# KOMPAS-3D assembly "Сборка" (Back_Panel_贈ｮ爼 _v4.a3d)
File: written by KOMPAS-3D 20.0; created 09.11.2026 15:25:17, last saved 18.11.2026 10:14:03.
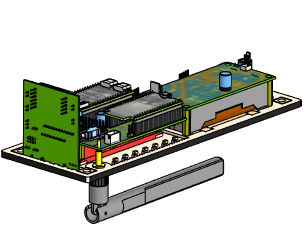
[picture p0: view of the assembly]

Document properties: Полное имя файла: D:\RicWork\Project-EPS32\box_compas\сборки компонентов\Back_Panel_Сборка_v4.a3d

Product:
- Part/product: Сборка
    Масса: 1.56344
  - Component [assembly]: Сборка  | pos. 18  | Масса: 0.0580575; Раздел спецификации: Сборочные единицы; source file: кондуктор под 3 кнопки asm.a3d
  - Component [detail]: Деталь  | pos. 15  | Масса: 0.000148431; Раздел спецификации: Детали; source file: ..\прочее\Латунные рифленые гайки HUI JI.m3d
  - Component [detail]: Деталь  | pos. 16  | Масса: 0.000148431; Раздел спецификации: Детали; source file: ..\прочее\Латунные рифленые гайки HUI JI.m3d
  - Component [detail]: Деталь  | pos. 14  | Масса: 0.000148431; Раздел спецификации: Детали; source file: ..\прочее\Латунные рифленые гайки HUI JI.m3d
  - Component [detail]: Деталь  | pos. 13  | Масса: 0.000148431; Раздел спецификации: Детали; source file: ..\прочее\Латунные рифленые гайки HUI JI.m3d
  - Component [detail]: Деталь  | pos. 10  | Материал: Фанера, береза,ФСФ ВВ/С ГОСТ 3916.1-2018 (density 760 kg/m3); Масса: 0.0215078; Раздел спецификации: Детали; source file: ..\корпус\back_panel_v4.m3d
  - Component [detail]: Деталь  | pos. 1  | Масса: 0.0866709; Раздел спецификации: Детали; source file: ..\корпус\крышка на батарейный отсек v4.m3d
  - Component [detail]: Деталь  | pos. 3  | Масса: 0.0290543; Раздел спецификации: Детали; source file: ..\корпус\крышка на монитор v4.m3d
  - Component [assembly]: Сборка  | pos. 6  | Масса: 0.0719376; Раздел спецификации: Сборочные единицы; source file: панель под энкодеры v4 asm.a3d
  - Component [assembly]: Сборка  | pos. 11  | Масса: 0.120303; Раздел спецификации: Сборочные единицы; source file: ..\wifi\antenna wifi_asm.a3d
  - Component [assembly]: Сборка  | pos. 9  | Масса: 0.317065; Раздел спецификации: Сборочные единицы; source file: MotherBoard dual cpu with IKI9341_81_50 asm.a3d
  - Component [assembly]: Сборка  | pos. 4  | Масса: 0.272217; Раздел спецификации: Сборочные единицы; source file: MotherBoard dual cpu with IKI9341_86_50 asm.a3d
  - Component [assembly]: Сборка  | pos. 8  | Масса: 0.445153; Раздел спецификации: Сборочные единицы; source file: ..\ups 18650\my_ups_asm v2 +.a3d
  - Component [assembly]: Сборка  | pos. 7  | Масса: 0.0902695; Раздел спецификации: Сборочные единицы; source file: ..\аудио\audio board asm.a3d
  - Component [assembly]: Сборка  | pos. 19  | Масса: 0.0506114; Раздел спецификации: Сборочные единицы; source file: кондуктор под 2 кнопки и заглушку asm.a3d

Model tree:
1. Эскиз:2  (with: Элемент выдавливания:10, Элемент выдавливания:72)
2. Эскиз:5  (with: Элемент выдавливания:1, Скругление:1)
3. Эскиз:6  (with: Элемент выдавливания:1, Элемент выдавливания:46, Элемент выдавливания:6, Элемент выдавливания:2, Элемент выдавливания:3, Элемент выдавливания:48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)

Referenced files in D:\RicWork\Project-EPS32\box_compas\корпус\: крышка на батарейный отсек v4.m3d, крышка на монитор v4.m3d, back_panel_v4.m3d
Referenced files in D:\RicWork\Project-EPS32\box_compas\сборки компонентов\: MotherBoard dual cpu with IKI9341_86_50 asm.a3d, панель под энкодеры v4 asm.a3d, MotherBoard dual cpu with IKI9341_81_50 asm.a3d, кондуктор под 3 кнопки asm.a3d, кондуктор под 2 кнопки и заглушку asm.a3d
Referenced files in D:\RicWork\Project-EPS32\box_compas\аудио\: audio board asm.a3d
Referenced files in D:\RicWork\Project-EPS32\box_compas\ups 18650\: my_ups_asm v2 +.a3d
Referenced files in D:\RicWork\Project-EPS32\box_compas\wifi\: antenna wifi_asm.a3d
Referenced files in D:\RicWork\Project-EPS32\box_compas\прочее\: Латунные рифленые гайки HUI JI.m3d
Referenced files in D:\myProjects\Progect_esp32\box_compas\прочее\: Латунные рифленые гайки HUI JI.m3d
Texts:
  Точка начала. Х
  Точка начала. Y
  Точка начала. Z
  Деталь (1)
  Деталь (2)
  Деталь (3)
  Деталь (4)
